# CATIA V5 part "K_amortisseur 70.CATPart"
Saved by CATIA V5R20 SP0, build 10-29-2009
Part number: amortisseur 70
Publications: "longueur verin commande", "demi largeur balancier", "epaisseur pieces", "demi largeur tige", "Plan.-55", "liaison 51/70 sur 70", "Droite.1"
Bounding box of the stored display mesh (mm): x -80 to 0, y -519.999 to 100.367, z 481.591 to 689.98
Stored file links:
  G:\Khaled_CFAO_2011\SIL\SIL_GR2\mdardier\Khaled\CAD_ThinkMOTION\K_amortisseur 70.CATPart
  G:\Khaled_CFAO_2011\SIL\SIL_GR2\mdardier\Khaled\CAD_ThinkMOTION\K_ass_tandem.CATProduct
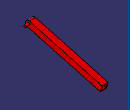
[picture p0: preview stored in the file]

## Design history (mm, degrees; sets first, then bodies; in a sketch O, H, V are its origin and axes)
External parameters (linked from other documents)
  `External.longueur verin commande` = 620 mm
  `External.demi largeur balancier` = 50 mm
  `External.epaisseur pieces` = 30 mm
  `External.demi largeur tige` = 17.5 mm
Set1
  Plane1 "Plan.-55": linked copy from another document
  Point1 "liaison 51/70 sur 70": linked copy from another document
  Line1: linked copy from another document
Body1 (main body)
  Sketch1 on Plane1, origin (-55, 0, 0), H (0, 1, 0), V (0, 0, 1)
    construction line L1 (-495, 665) -> (103.4919, 503.1128)
    point P1 (-495, 665)
    line L2 (-488.4723, 689.1327) -> (100.3665, 529.8567)
    line L3 (87.3111, 481.5912) -> (-501.5277, 640.8673)
    arc A1 centre (-495, 665) radius 25 from (-501.5277, 640.8673) to (-488.4723, 689.1327) cw
    point P4 (100.3665, 529.8567)
    point P5 (87.3111, 481.5912)
    reference projected point E1 (-495, 665) from Point1
    reference projected line E2 (-495, 665) -> (103.4919, 503.1128) from Line1
    line L4 (100.3665, 529.8567) -> (87.3111, 481.5912)
    point P7 (87.3111, 481.5912)
    point P8 (100.3665, 529.8567)
    distance L1 L2 = 25 {= `External.demi largeur balancier` /2}
    length L2 = 610 {= `External.longueur verin commande` -0.01}
    tangency: A1 L2, A1 L3
    coincidence: P1 E1, P7 L3, P8 P4, P5 P7
    parallelism: L1 E2
    perpendicularity: L4 L1, L4 L2, L3 L4
  Pad1: profile Sketch1, direction (1, 0, 0), length 25 {= `External.demi largeur balancier` /2}, mirrored extent
  Sketch2 on end face of Pad1, origin (-30, 0, 0), H (0, 1, 0), V (0, 0, 1)
    circle A1 centre (-495, 665) radius 10
    point P1 (-495, 665)
    reference projected point E1 (-495, 665) from Point1
    radius A1 = 10 {= `External.demi largeur balancier` /5}
    coincidence: P1 E1
  Pad2: profile Sketch2, direction (1, 0, 0), length 30 {= `External.epaisseur pieces`}
  Sketch3 on face of Pad1 from Sketch1.L4, origin (0, -40.0268, 10.8269), H (-1, 0, 0), V (0, 0.2611, 0.9653)
    line L1 (36.5, 531.1822) -> (73.5, 531.1822)
    line L2 (73.5, 531.1822) -> (73.5, 494.1822)
    line L3 (73.5, 494.1822) -> (36.5, 494.1822)
    line L4 (36.5, 494.1822) -> (36.5, 531.1822)
    reference projected line E1 (80, 537.6822) -> (30, 537.6822) from edge [face of Pad1 from Sketch1.L2 | face of Pad1 from Sketch1.L4]
    reference projected line E2 (80, 480.5419) -> (80, 544.8225) from edge [start face of Pad1 | face of Pad1 from Sketch1.L4]
    reference projected line E3 (30, 480.5419) -> (30, 544.8225) from edge [face of Pad1 from Sketch1.L4 | end face of Pad1]
    reference projected line E4 (80, 487.6822) -> (30, 487.6822) from edge [face of Pad1 from Sketch1.L4 | face of Pad1 from Sketch1.L3]
    distance L1 E1 = 6.5 {= `External.demi largeur balancier` /2-`External.demi largeur tige` -0.001}
    distance L2 E2 = 6.5 {= `External.demi largeur balancier` /2-`External.demi largeur tige` -0.001}
    distance L4 E3 = 6.5 {= `External.demi largeur balancier` /2-`External.demi largeur tige` -0.001}
    distance L3 E4 = 6.5 {= `External.demi largeur balancier` /2-`External.demi largeur tige` -0.001}
    horizontal: L1 H, L3 H
    vertical: L2 V, L4 V
  Pocket1: profile Sketch3, direction (0, -0.9653, 0.2611), length 610 {= `External.longueur verin commande` -0.01}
